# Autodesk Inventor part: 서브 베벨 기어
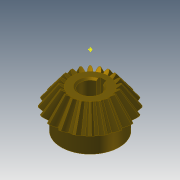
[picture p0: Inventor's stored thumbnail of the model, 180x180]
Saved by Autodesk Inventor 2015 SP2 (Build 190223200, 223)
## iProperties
Created: 2014-10
Part Number: 서브 베벨 기어
Material: 강철
Document SubType Name: Modeling
Designer: KYOUNG IL JANG
Categories: <?xml version="1.0" encoding="UTF-16"?> <MemberInstance><Categories><FamilyTemplate><FamilyTemplateParameter ValueType="xs:double" Id="1" ObjectReferenceKey="da
Mass: 134.694 g
Surface Area: 63.6518 cm^2
Volume: 17.1585 cm^3
Density: 7.85 g/cm^3
Appearance: 얼룩무늬
CustomPartVersion: 1
Company: 한국ATC센터
Author: KYOUNG IL JANG
Revision Number: 1
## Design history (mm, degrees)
node "맨 위 점"
node "메쉬 평면2"
sketch "톱니 본체 스케치"
  geometry: L1 (0, 0)-(18.003, -31.331); L2 (18.003, -31.331)-(21.664, -28.891); L3 (21.664, -28.891)-(0, 0); L4 (20, -30)-(0, 0); L5 (10.813, -18.818)-(13.012, -17.352); L6 (18.003, -31.331)-(10.813, -18.818); L7 (21.664, -28.891)-(13.012, -17.352); L8 (0, -39.387)-(0, 6.564) reference; L9 (0, -30)-(21.664, -30)
  constraints: 16 end point, 4 point on line, 3 perpendicular, 2 collinear, 1 horizontal alignment, 1 vertical alignment
  dimensions: "d0" = 40 diameter of L4.start L8 (= da_de); "d1" = 36.00616 diameter of L1.end L8 (= da_dfe); "d2" = 43.3282 diameter of L2.end L8 (= da_dae); "d3" = 14.4 distance between parallel lines of L2 L5 (= da_b); "d4" = 28.8906 vertical distance of L2.end L1.start (= da_ve)
revolve "톱니 본체" sketch "톱니 본체 스케치" stored, may be unused: angle "d5" = 90 deg
node "시작점"
node "톱니 평면"
sketch "시작 스케치"
  geometry: L1 (0, -23.505)-(0, 10.645) reference; L2 (-0.834, -2.928)-(0.834, -2.928); A1 r 8.898 centre (-9.698, -3.713) between (-0.834, -2.928) and (-3.903, 3.04); A2 r 8.898 centre (9.698, -3.713) between (3.903, 3.04) and (0.834, -2.928); A3 r 27.357 centre (0, -24.037) between (3.903, 3.04) and (-3.903, 3.04); 1 further point
  constraints: 6 point on circle, 3 centre point, 3 symmetric about line, 2 end point, 1 coincident, 1 perpendicular, 1 other
  dimensions: "d7" = 8.89846 radius of A1 (= fd_rr); "d8" = 9.69794 horizontal distance of point (0, -24.037) A1.centre (= fd_x); "d9" = 20.32439 vertical distance of point (0, -24.037) A1.centre (= fd_y); "d57" = 27.35701 radius of A3 (= 0.5 x fd_dva + 0.3 x da_he); "d58" = 21.10901 distance from line of A3.centre L2 (= 0.5 x fd_dva - 1.12 x da_he)
node "끝점"
  node "끝 평면"
sketch "3D 스케치 오른쪽"
  node "Helical Curve Right" dims "d65" = 229.90621 (computed from da_dm, da_delta, da_beta), "d66" = 31.5, "d67" = 40 (= da_de), "d68" = -5.88003 (= -da_delta), "d69" = 12.16458 (computed from fd_loft, da_delta)
node "끝 평면 오른쪽"
sketch "끝 스케치 오른쪽"
  geometry: L1 (0, -22.649)-(0, 12.15) reference; L2 (-0.497, -1.72)-(0.497, -1.72); A1 r 5.299 centre (-5.775, -2.187) between (-0.497, -1.72) and (-2.324, 1.834); A2 r 5.299 centre (5.775, -2.187) between (2.324, 1.834) and (0.497, -1.72); A3 r 16.291 centre (0, -14.29) between (2.324, 1.834) and (-2.324, 1.834); 1 further point
  constraints: 6 point on circle, 3 centre point, 3 symmetric about line, 2 end point, 1 coincident, 1 perpendicular, 1 other
  dimensions: "d70" = 5.77526 horizontal distance of A3.centre A1.centre (computed from fd_x, fd_ratio); "d71" = 12.10346 vertical distance of point (0, -14.29) A1.centre (computed from fd_y, fd_ratio); "d72" = 5.29916 radius of A1 (computed from fd_rr, fd_ratio); "d73" = 12.57071 distance from line of point (0, -14.29) L2 (computed from d58, fd_ratio); "d74" = 16.29149 radius of A3 (computed from d57, fd_ratio)
feature "로프트 오른쪽" sketch "끝 스케치 오른쪽" dims "d75" = 0, "d77" = 0, "d79" = 0, "d80" = 90 deg, "d85" = 20, "d92" = 90 deg, "d93" = 90 deg, "da_teethtype" = 0 [user parameter]
sketch "3D 스케치 왼쪽"
  node "Helical Curve Left" dims "d26" = 229.90621 (computed from da_dm, da_delta, da_beta), "d27" = 12.16458 (computed from fd_loft, da_delta), "d28" = 40 (= da_de), "d29" = -5.88003 (= -da_delta)
node "끝 평면 왼쪽"
sketch "끝 스케치 왼쪽" dims "d56" = 10.82768 (derived)
  geometry: L1 (0, -35.087)-(0, 18.089) reference; L2 (-0.497, -1.716)-(0.497, -1.716); A1 r 5.299 centre (-5.775, -2.183) between (-0.497, -1.716) and (-2.324, 1.838); A2 r 5.299 centre (5.775, -2.183) between (2.324, 1.838) and (0.497, -1.716); A3 r 16.291 centre (0, -14.287) between (2.324, 1.838) and (-2.324, 1.838); 2 further points; 1 other entity
  constraints: 6 point on circle, 3 centre point, 3 symmetric about line, 2 end point, 1 coincident, 2 other
  dimensions: "d30" = 5.29916 radius of A1 (computed from fd_rr, fd_ratio); "d31" = 5.77526 horizontal distance of point (0, -14.287) A1.centre (computed from fd_x, fd_ratio); "d32" = 12.10346 vertical distance of A1.centre point (0, -14.287) (computed from fd_y, fd_ratio); "d61" = 16.29149 radius of A3 (computed from d57, fd_ratio); "d62" = 12.57071 distance from line of point (0, -14.287) L2 (computed from d58, fd_ratio)
feature "로프트 왼쪽" sketch "끝 스케치 왼쪽" dims "d35" = 0, "d37" = 0, "d39" = 0, "d40" = 90 deg, "d84" = 10, "d90" = 90 deg, "d91" = 90 deg, "da_teethtype" = 0 [user parameter]
sketch "본체 스케치"
  geometry: L1 (0, -35.038)-(0, -19.531) reference; L2 (18.003, -31.331)-(10.813, -18.818) reference; L3 (10.813, -18.818)-(0, -18.818); L4 (18.003, -31.331)-(0, -31.331)
  constraints: 4 end point, 2 perpendicular, 2 point on line
revolve "본체 고정" sketch "본체 스케치" stored, may be unused: angle "d46" = 90 deg
feature "피치 지름" dims angle "d47" = 90 deg
sketch "스케치8"
  geometry: C1 r 17 at (0, 0); 1 further point
  constraints: 1 centre point, 1 coincident
  dimensions: "d94" = 34 diameter of C1
extrude "돌출1" join sketch "스케치8" distance "d95" = 10; taper "d96" = 0 deg
sketch "스케치9"
  geometry: 1 further point
hole "구멍1" sketch "스케치9" at (0, 0) diameter "d97" = 12; stored, may be unused: countersink angle "d101" = 90 deg, drill point angle "d103" = 118 deg; dims "d98" = 6, "d99" = 4, "d100" = 2, "d102" = 8
sketch "스케치10"
  geometry: 1 further point
sketch "스케치11"
  geometry: 1 further point
sketch "스케치12"
  geometry: L1 (-2, 5.657)-(-2, 7.8); L2 (-2, 7.8)-(2, 7.8); L3 (2, 7.8)-(2, 5.657); A1 r 6 centre (0, 0) between (-2, 5.657) and (2, 5.657) reference; 1 further point
  constraints: 6 end point, 2 parallel, 2 point on circle, 1 perpendicular, 1 vertical
  dimensions: "d104" = 4 distance of L1.end L2.end; "d105" = 13.8 dimension on A1 L2
extrude "돌출2" cut sketch "스케치12" stored distance "d106" = 7; taper "d107" = 0 deg
chamfer "모따기1" distance "d108" = 1; stored, may be unused: second distance "d109" = 2, angle "d110" = 45 deg
body "Solid1"
feature "로프트" dims "d17" = 0, "d18" = 90 deg, "d19" = 0, "d20" = 90 deg, "d89" = 0, "da_teethtype" = 0 [user parameter]
pattern_circular "원형 패턴" dims angle "d22" = 360 deg, "d88" = 0, "da_teethtype" = 0 [user parameter]
pattern_circular "원형 패턴 오른쪽" dims angle "d82" = 360 deg, "da_teethtype" = 0 [user parameter]
pattern_circular "원형 패턴 왼쪽" dims angle "d42" = 360 deg, "da_teethtype" = 0 [user parameter]
sketch "끝 스케치"
  geometry: L1 (0, -15.359)-(0, 6.983) reference; L2 (-0.497, -1.72)-(0.497, -1.72); A1 r 5.299 centre (-5.775, -2.187) between (-0.497, -1.72) and (-2.324, 1.834); A2 r 5.299 centre (5.775, -2.187) between (2.324, 1.834) and (0.497, -1.72); A3 r 16.291 centre (0, -14.29) between (2.324, 1.834) and (-2.324, 1.834); 1 further point
  constraints: 6 point on circle, 3 centre point, 3 symmetric about line, 2 end point, 1 coincident, 1 other
  dimensions: "d12" = 5.29916 radius of A1 (computed from fd_rr, fd_ratio); "d15" = 5.77526 horizontal distance of A1.centre point (0, -14.29) (computed from fd_x, fd_ratio); "d16" = 12.10346 vertical distance of A1.centre point (0, -14.29) (computed from fd_y, fd_ratio); "d59" = 16.29149 radius of A3 (computed from d57, fd_ratio); "d60" = 12.57071 distance from line of A3.centre L2 (computed from d58, fd_ratio)
sketch "Sketch6"
  geometry: L1 (20, -30)-(0, 0) reference; L2 (0, -37.8)-(0, 6.3) reference
body "Srf1"
other parameters: "da_b" = 14.4 [user parameter; used in 2 equation terms], "da_de" = 40 [user parameter; used in 4 equation terms], "da_dae" = 43.3282 [user parameter; used in 2 equation terms], "da_dfe" = 36.00616 [user parameter; used in 1 equation term], "da_le" = 36.05551 [user parameter; used in 1 equation term], "da_omega" = 90 deg [user parameter; used in 1 equation term], "da_beta" = 0 [user parameter; used in 2 equation terms], "da_delta" = 5.88003 [user parameter; used in 8 equation terms], "da_alpha" = 20 deg [user parameter; used in 2 equation terms], "da_he" = 4.4 [user parameter; used in 4 equation terms], "da_ve" = 28.8906 [user parameter; used in 1 equation term], "fd_dv" = 48.07402 (computed from da_de, da_delta) [user parameter; used in 1 equation term], "fd_dva" = 52.07402 (computed from da_dae, da_delta) [user parameter; used in 3 equation terms], "fd_dvb" = 45.1748 (computed from fd_dv, da_alpha) [user parameter; used in 2 equation terms], "da_zv" = 240.37008 [user parameter; used in 1 equation term], "fd_loft" = 14.62 (= da_b + 0.05 x da_he) [user parameter; used in 4 equation terms], "fd_ratio" = 5.95514 (computed from da_le, fd_loft) [user parameter; used in 15 equation terms], "fd_rr" = 8.89846 (computed from fd_dd, fd_dvb) [user parameter; used in 6 equation terms], "fd_angle" = 0.66075 (computed from da_zv) [user parameter; used in 4 equation terms], "fd_x1" = 1.58709 (computed from da_dvw, fd_angle) [user parameter; used in 1 equation term], "fd_y1" = 23.98456 (computed from da_dvw, fd_angle) [user parameter; used in 1 equation term], "fd_x2" = 8.11084 (computed from fd_rr, fd_angle2, fd_angle) [user parameter; used in 1 equation term], "fd_y2" = 3.66016 (computed from fd_rr, fd_angle2, fd_angle) [user parameter; used in 1 equation term], "fd_x" = 9.69794 (= fd_x1 + fd_x2) [user parameter; used in 4 equation terms], "fd_y" = 20.32439 (= fd_y1 - fd_y2) [user parameter; used in 4 equation terms], "fd_angle2" = 3.57832 (computed from fd_dvb, fd_dd, da_alpha) [user parameter; used in 2 equation terms], "fd_dd" = 48.55402 (= fd_dva - 0.8 x da_he) [user parameter; used in 2 equation terms], "da_dvw" = 48.07402 [user parameter; used in 2 equation terms], "d11" = 14.62 (= fd_loft), "da_dm" = 32.01232 [user parameter; used in 2 equation terms], "da_x" = 0 [user parameter], "da_m" = 2 [user parameter], "d48" = 0, "d49" = 0, "d50" = 90 deg (= da_omega), "d51" = 9 deg (computed from da_z), "d52" = 0, "d53" = 0, "d54" = 0
